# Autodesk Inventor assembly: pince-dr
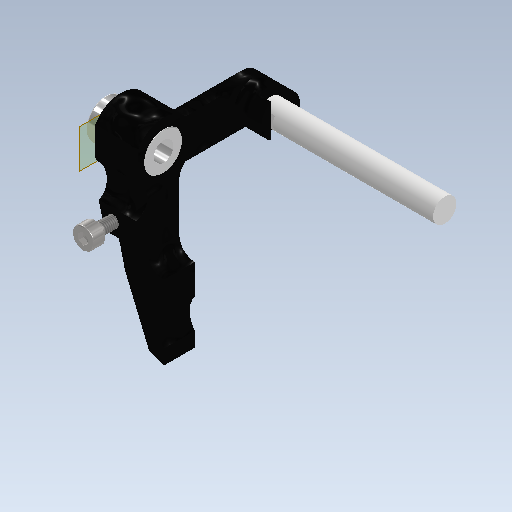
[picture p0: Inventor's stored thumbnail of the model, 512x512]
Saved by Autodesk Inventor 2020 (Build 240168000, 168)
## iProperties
Created: 2023-10
Part Number: pince-dr
Document SubType Name: Assembly
Designer: bruno
Mass: 9.25906 g
Surface Area: 52.2227 cm^2
Volume: 6.62025 cm^3
Density: 1.3986 g/cm^3
Author: bruno
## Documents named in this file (6)
- C:\Users\bruno\Documents\1-Cours-2023-24\Maquettes-Inventor\Pince-robot-Dobot\pince-dr.iam
- C:\Users\bruno\Documents\1-Cours-2023-24\Maquettes-Inventor\Pince-robot-Dobot\pince-d.ipt
- C:\Users\bruno\Documents\1-Cours-2023-24\Maquettes-Inventor\Pince-robot-Dobot\Tige-verin.ipt
- C:\Users\bruno\Documents\1-Cours-2023-24\Maquettes-Inventor\Pince-robot-Dobot\Douille.ipt
- C:\Users\bruno\Documents\Inventor\Content Center Files\R2020\fr-FR\KS B 1003\KS B 1003 - M 2 x 5.ipt
- C:\Users\bruno\Documents\Inventor\Content Center Files\R2020\fr-FR\KS B 1003\KS B 1003 - M 3 x 10.ipt
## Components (5 placed, 5 different names)
1. pince-d:1 — Placage:1, Affleurement:1, Placage:2, Placage:3, Placage:4, Logement:1, Placage:5, Placage:6
2. Tige-verin:1 — Placage:1, Placage:3, Placage:4
3. Douille:1 — Affleurement:1, Placage:2
4. KS B 1003 - Métrique M 2 x 5:1 — Logement:1
5. KS B 1003 - Métrique M 3 x 10:1 — Placage:5, Placage:6
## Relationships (8: Mate 6, Flush 1, Insert 1)
- Placage:1 [Mate]: pince-d:1 ↔ Tige-verin:1
- Affleurement:1 [Flush]: pince-d:1 ↔ Douille:1
- Placage:2 [Mate]: pince-d:1 ↔ Douille:1
- Placage:3 [Mate]: pince-d:1 ↔ Tige-verin:1
- Placage:4 [Mate]: pince-d:1 ↔ Tige-verin:1
- Logement:1 [Insert]: pince-d:1 ↔ KS B 1003 - Métrique M 2 x 5:1
- Placage:5 [Mate]: pince-d:1 ↔ KS B 1003 - Métrique M 3 x 10:1
- Placage:6 [Mate]: pince-d:1 ↔ KS B 1003 - Métrique M 3 x 10:1
